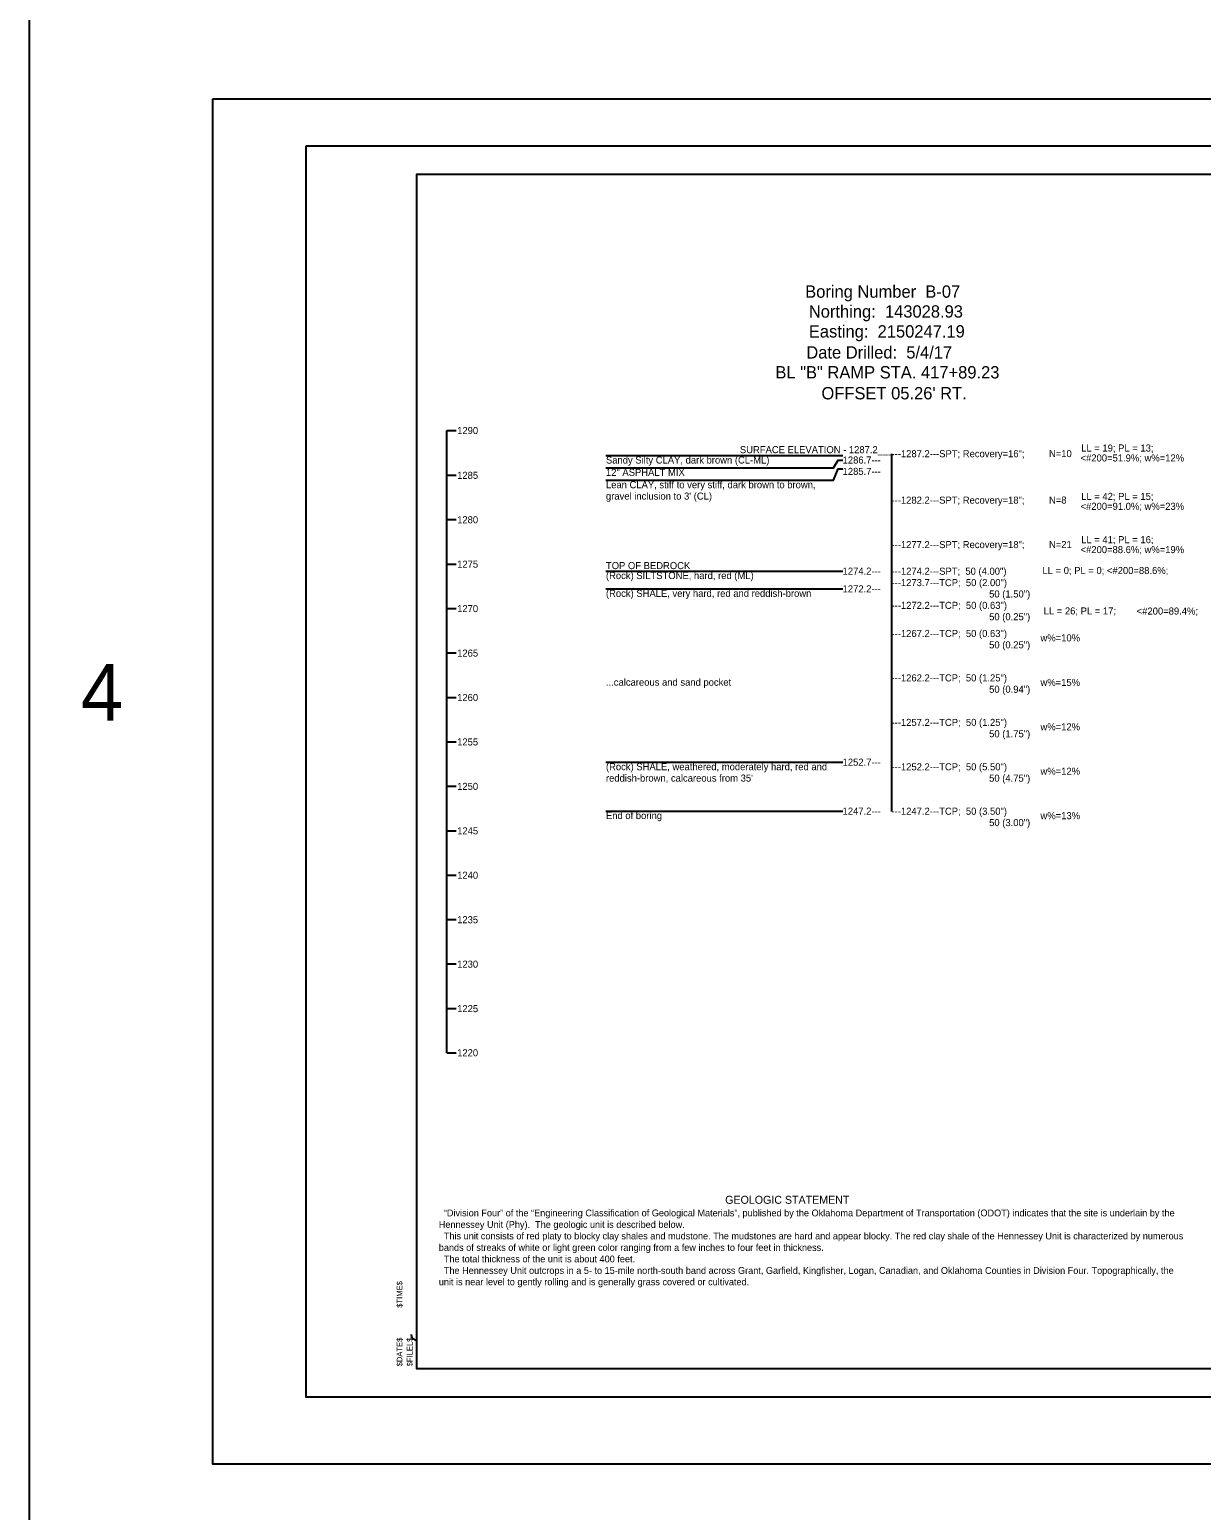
# Model space of a CAD drawing. Extents: x 2150162 to 2150245, y 143729 to 143865.
# Drawn here: x 2150161.57 to 2150182.18, y 143757.78 to 143783.81 of the extents above; entities that cross this region are included whole.
import ezdxf

# ---------------------------------------------------------------- set-up
doc = ezdxf.new("R2010")
doc.units = 0
for name, color, linetype in [('Bridge Border', 7, 'Continuous'), ('Default', 7, 'Continuous'), ('S', 7, 'Continuous'), ('SHT_Plot_Shape_Full', 7, 'Continuous'), ('SHT_Plot_Shape_Half', 7, 'Continuous'), ('SHT_Plot_Stamp', 7, 'Continuous'), ('SHT_Sheet_Border', 7, 'Continuous'), ('Text', 7, 'Continuous')]:
    doc.layers.add(name, color=color, linetype=linetype)

# ---------------------------------------------------------------- blocks, each defined once
blk = doc.blocks.new('Stamp_Plot_Stamp')
at = {"layer": 'SHT_Plot_Stamp'}
for s, p in [('$TIME$', (1.695, 1.572)), ('$DATE$', (1.695, 0.542)), ('$FILEL$', (1.873, 0.542))]:
    blk.add_text(s, height=0.1, rotation=90, dxfattribs=at).set_placement(p)

msp = doc.modelspace()

# ---------------------------------------------------------------- linework, layer by layer
at = {"layer": 'Bridge Border'}
msp.add_arc((2150168.379, 143760.87), 0.1, 180, 270, dxfattribs=at)
at = {"layer": 'Default'}
msp.add_line((2150168.905, 143765.823), (2150168.905, 143776.761), dxfattribs=at)
for points in [[(2150168.905, 143776.761), (2150169.071, 143776.761)], [(2150171.704, 143776.323), (2150175.871, 143776.323)], [(2150176.723, 143776.351), (2150176.723, 143770.067)], [(2150171.704, 143776.107), (2150175.704, 143776.107), (2150175.787, 143776.245), (2150175.871, 143776.245)], [(2150171.704, 143775.89), (2150175.704, 143775.89), (2150175.787, 143776.089), (2150175.871, 143776.089)], [(2150168.905, 143775.979), (2150169.071, 143775.979)], [(2150168.905, 143775.198), (2150169.071, 143775.198)], [(2150168.905, 143774.417), (2150169.071, 143774.417)], [(2150168.905, 143774.417), (2150169.071, 143774.417)], [(2150171.704, 143774.292), (2150175.871, 143774.292)], [(2150171.704, 143773.98), (2150175.871, 143773.98)], [(2150168.905, 143773.636), (2150169.071, 143773.636)], [(2150168.905, 143772.854), (2150169.071, 143772.854)], [(2150168.905, 143772.073), (2150169.071, 143772.073)], [(2150168.905, 143771.292), (2150169.071, 143771.292)], [(2150171.704, 143770.933), (2150175.871, 143770.933)], [(2150168.905, 143770.511), (2150169.071, 143770.511)], [(2150171.704, 143770.073), (2150175.871, 143770.073)], [(2150168.905, 143769.729), (2150169.071, 143769.729)], [(2150168.905, 143768.948), (2150169.071, 143768.948)], [(2150168.905, 143768.167), (2150169.071, 143768.167)], [(2150168.905, 143767.386), (2150169.071, 143767.386)], [(2150168.905, 143766.604), (2150169.071, 143766.604)], [(2150168.905, 143765.823), (2150169.071, 143765.823)]]:
    msp.add_lwpolyline(points, dxfattribs=at)
at = {"layer": 'S'}
msp.add_lwpolyline([(2150161.568, 143784.341), (2150203.404, 143784.341), (2150203.404, 143729.315), (2150161.568, 143729.315)], close=True, dxfattribs=at)
at = {"layer": 'SHT_Plot_Shape_Full'}
msp.add_lwpolyline([(2150164.792, 143782.595), (2150200.792, 143782.595), (2150200.792, 143758.595), (2150164.792, 143758.595)], close=True, dxfattribs=at)
at = {"layer": 'SHT_Plot_Shape_Half'}
msp.add_lwpolyline([(2150166.429, 143781.77), (2150200.429, 143781.77), (2150200.429, 143759.77), (2150166.429, 143759.77)], close=True, dxfattribs=at)
at = {"layer": 'SHT_Sheet_Border'}
msp.add_lwpolyline([(2150199.879, 143760.27), (2150168.379, 143760.27), (2150168.379, 143781.27), (2150199.879, 143781.27)], close=True, dxfattribs=at)

# ---------------------------------------------------------------- block references
at = {"layer": 'SHT_Plot_Stamp'}
msp.add_blockref('Stamp_Plot_Stamp', (2150166.429, 143759.77), dxfattribs=at)

# ---------------------------------------------------------------- texts
at = {"layer": 'Default'}
for s, height, p in [('Boring Number  B-07', 0.217, (2150175.208, 143779.098)), ('Northing:  143028.93', 0.217, (2150175.272, 143778.748)), ('Easting:  2150247.19', 0.217, (2150175.272, 143778.398)), ('Date Drilled:  5/4/17', 0.217, (2150175.228, 143778.029)), ('BL "B" RAMP STA. 417+89.23', 0.217, (2150174.684, 143777.679)), ("OFFSET 05.26' RT.", 0.217, (2150175.494, 143777.311)), ('1290', 0.124, (2150169.087, 143776.702)), ('LL = 19; PL = 13;', 0.124, (2150180.062, 143776.394)), ('Sandy Silty CLAY, dark brown (CL-ML)', 0.124, (2150171.704, 143776.183)), ('SURFACE ELEVATION - 1287.2___', 0.124, (2150174.06, 143776.365)), ('1286.7---', 0.124, (2150175.866, 143776.183)), ('---1287.2---SPT; Recovery=16";', 0.124, (2150176.726, 143776.294)), ('N=10', 0.124, (2150179.495, 143776.296)), ('<#200=51.9%; w%=12%', 0.124, (2150180.051, 143776.219)), ('1285', 0.124, (2150169.087, 143775.914)), ('12" ASPHALT MIX', 0.124, (2150171.704, 143775.966)), ('1285.7---', 0.124, (2150175.866, 143775.983)), ('Lean CLAY, stiff to very stiff, dark brown to brown,', 0.124, (2150171.704, 143775.749)), ("gravel inclusion to 3' (CL)", 0.124, (2150171.704, 143775.549)), ('---1282.2---SPT; Recovery=18";', 0.124, (2150176.726, 143775.478)), ('N=8', 0.124, (2150179.495, 143775.479)), ('<#200=91.0%; w%=23%', 0.124, (2150180.051, 143775.369)), ('LL = 42; PL = 15;', 0.124, (2150180.062, 143775.544)), ('1280', 0.124, (2150169.087, 143775.133)), ('---1277.2---SPT; Recovery=18";', 0.124, (2150176.726, 143774.696)), ('N=21', 0.124, (2150179.495, 143774.698)), ('<#200=88.6%; w%=19%', 0.124, (2150180.051, 143774.608)), ('LL = 41; PL = 16;', 0.124, (2150180.062, 143774.783)), ('1275', 0.124, (2150169.087, 143774.352)), ('TOP OF BEDROCK', 0.124, (2150171.704, 143774.327)), ('(Rock) SILTSTONE, hard, red (ML)', 0.124, (2150171.704, 143774.152)), ('1274.2---', 0.124, (2150175.866, 143774.23)), ('---1274.2---SPT;  50 (4.00")', 0.124, (2150176.726, 143774.228)), ('LL = 0; PL = 0; <#200=88.6%;', 0.124, (2150179.381, 143774.241)), ('(Rock) SHALE, very hard, red and reddish-brown', 0.124, (2150171.704, 143773.839)), ('1272.2---', 0.124, (2150175.866, 143773.918)), ('---1273.7---TCP;  50 (2.00")', 0.124, (2150176.726, 143774.028)), ('50 (1.50")', 0.124, (2150178.443, 143773.828)), ('1270', 0.124, (2150169.087, 143773.571)), ('---1272.2---TCP;  50 (0.63")', 0.124, (2150176.726, 143773.628)), ('LL = 26; PL = 17;', 0.124, (2150179.402, 143773.53)), ('<#200=89.4%;', 0.124, (2150181.038, 143773.528)), ('50 (0.25")', 0.124, (2150178.443, 143773.428)), ('---1267.2---TCP;  50 (0.63")', 0.124, (2150176.726, 143773.134)), ('w%=10%', 0.124, (2150179.346, 143773.056)), ('1265', 0.124, (2150169.087, 143772.789)), ('50 (0.25")', 0.124, (2150178.443, 143772.934)), ('...calcareous and sand pocket', 0.124, (2150171.704, 143772.277)), ('---1262.2---TCP;  50 (1.25")', 0.124, (2150176.726, 143772.353)), ('w%=15%', 0.124, (2150179.346, 143772.274)), ('1260', 0.124, (2150169.087, 143772.008)), ('50 (0.94")', 0.124, (2150178.443, 143772.153)), ('---1257.2---TCP;  50 (1.25")', 0.124, (2150176.726, 143771.571)), ('w%=12%', 0.124, (2150179.346, 143771.493)), ('1255', 0.124, (2150169.087, 143771.227)), ('50 (1.75")', 0.124, (2150178.443, 143771.371)), ('(Rock) SHALE, weathered, moderately hard, red and', 0.124, (2150171.704, 143770.792)), ('1252.7---', 0.124, (2150175.866, 143770.871)), ('---1252.2---TCP;  50 (5.50")', 0.124, (2150176.726, 143770.79)), ('w%=12%', 0.124, (2150179.346, 143770.712)), ('1250', 0.124, (2150169.087, 143770.446)), ("reddish-brown, calcareous from 35'", 0.124, (2150171.704, 143770.592)), ('50 (4.75")', 0.124, (2150178.443, 143770.59)), ('End of boring', 0.124, (2150171.704, 143769.933)), ('1247.2---', 0.124, (2150175.866, 143770.011)), ('---1247.2---TCP;  50 (3.50")', 0.124, (2150176.726, 143770.009)), ('w%=13%', 0.124, (2150179.346, 143769.931)), ('1245', 0.124, (2150169.087, 143769.664)), ('50 (3.00")', 0.124, (2150178.443, 143769.809)), ('1240', 0.124, (2150169.087, 143768.883)), ('1235', 0.124, (2150169.087, 143768.102)), ('1230', 0.124, (2150169.087, 143767.321)), ('1225', 0.124, (2150169.087, 143766.539)), ('1220', 0.124, (2150169.087, 143765.763))]:
    msp.add_text(s, height=height, dxfattribs=at).set_placement(p)
at = {"layer": 'S'}
msp.add_text('4', height=1, dxfattribs=at).set_placement((2150162.468, 143771.662))
at = {"layer": 'Text'}
for s, height, p in [('GEOLOGIC STATEMENT', 0.14, (2150173.801, 143763.17)), ('  “Division Four” of the “Engineering Classification of Geological Materials”, published by the Oklahoma Department of Transportation (ODOT) indicates that the site is underlain by the ', 0.12, (2150168.764, 143762.949)), ('Hennessey Unit (Phy).  The geologic unit is described below. ', 0.12, (2150168.764, 143762.746)), ('bands of streaks of white or light green color ranging from a few inches to four feet in thickness. ', 0.12, (2150168.764, 143762.342)), ('  This unit consists of red platy to blocky clay shales and mudstone. The mudstones are hard and appear blocky. The red clay shale of the Hennessey Unit is characterized by numerous ', 0.12, (2150168.764, 143762.544)), ('  The total thickness of the unit is about 400 feet.', 0.12, (2150168.764, 143762.14)), ('  The Hennessey Unit outcrops in a 5- to 15-mile north-south band across Grant, Garfield, Kingfisher, Logan, Canadian, and Oklahoma Counties in Division Four. Topographically, the ', 0.12, (2150168.764, 143761.938)), ('unit is near level to gently rolling and is generally grass covered or cultivated.', 0.12, (2150168.764, 143761.738))]:
    msp.add_text(s, height=height, dxfattribs=at).set_placement(p)

doc.saveas('drawing.dxf')
